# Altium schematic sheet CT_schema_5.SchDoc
size 296 x 173 mm
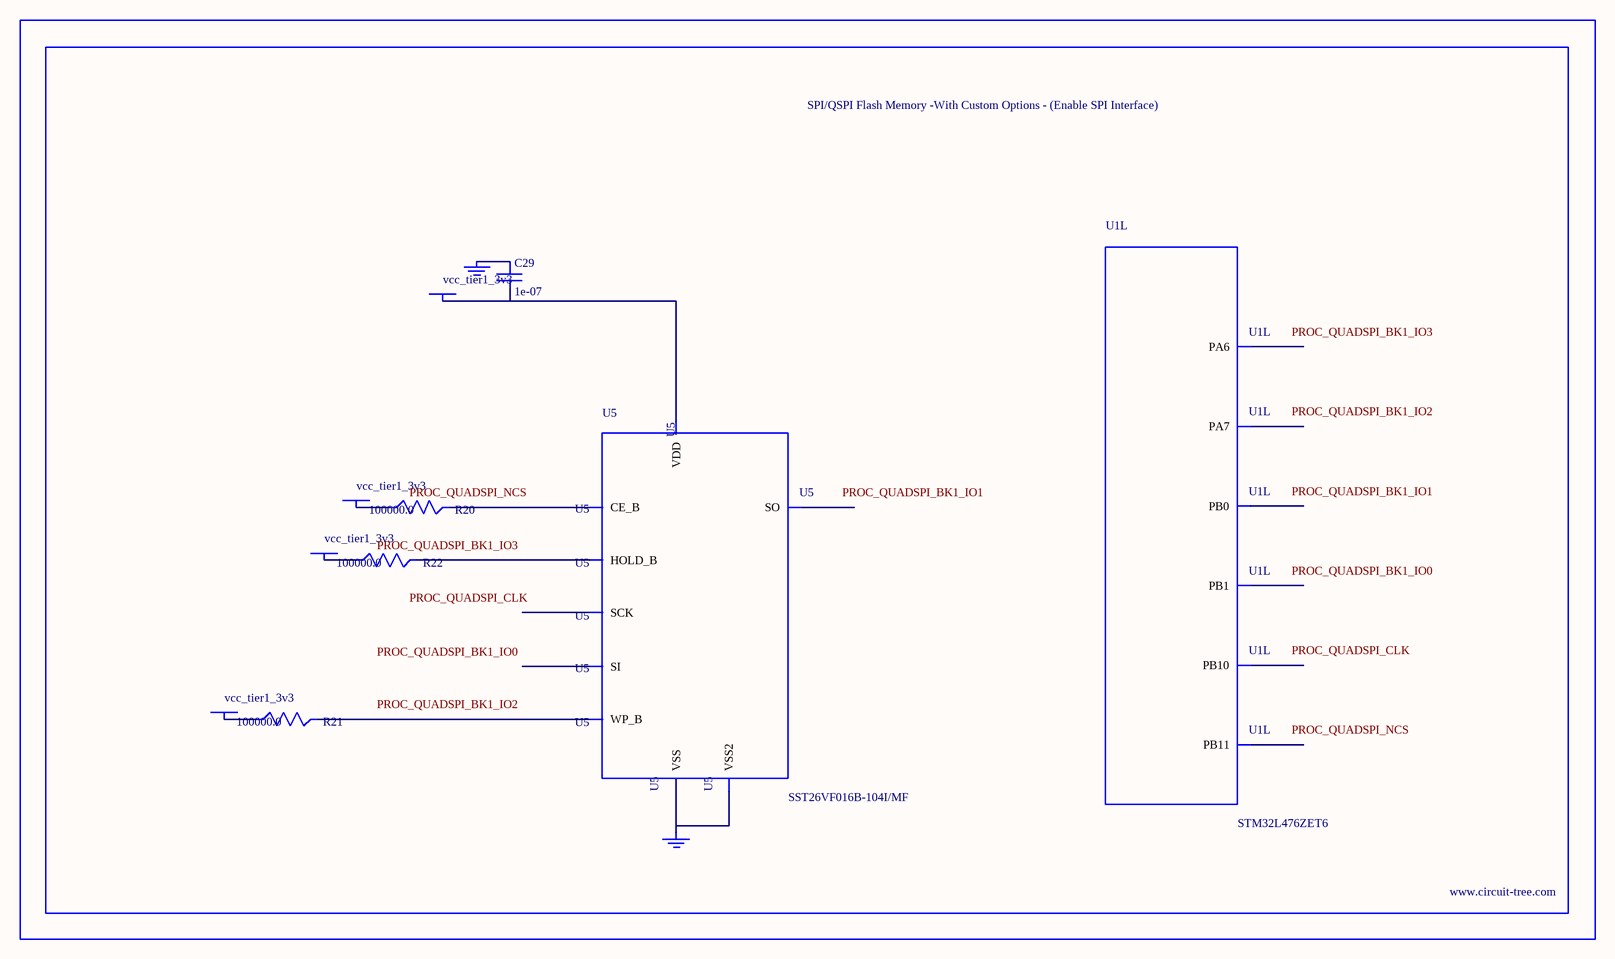
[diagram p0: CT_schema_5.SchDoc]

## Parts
BORDER4  (no value)
C29  1e-07  [C0402]
GND_INSTANCE_4_0  (no value)
GND_INSTANCE_4_1  (no value)
POWER_INSTANCE_4_0  vcc_tier1_3v3
POWER_INSTANCE_4_1  vcc_tier1_3v3
POWER_INSTANCE_4_2  vcc_tier1_3v3
POWER_INSTANCE_4_3  vcc_tier1_3v3
R20  100000.0  [R0603]
R21  100000.0  [R0603]
R22  100000.0  [R0603]
U1  STM32L476ZET6  [LQFP144]  (part L of 13)
U5  SST26VF016B-104I/MF  [WFDN-8]

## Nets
NetC29_1: C29.1 GND_INSTANCE_4_0.0(GND)
NetC29_2: C29.2 POWER_INSTANCE_4_3.0(PWR) U5.8(VDD)
NetGND_INSTANCE_4_1_0: GND_INSTANCE_4_1.0(GND) U5.4(VSS) U5.9(VSS2)
NetPOWER_INSTANCE_4_0_0: POWER_INSTANCE_4_0.0(PWR) R20.1
NetPOWER_INSTANCE_4_1_0: POWER_INSTANCE_4_1.0(PWR) R21.1
NetPOWER_INSTANCE_4_2_0: POWER_INSTANCE_4_2.0(PWR) R22.1
NetR20_2: R20.2 U5.1(CE_B)
NetR21_2: R21.2 U5.3(WP_B)
NetR22_2: R22.2 U5.7(HOLD_B)

Not connected (* = marked no-connect by the designer): U1 42(PA6) 43(PA7) 46(PB0) 47(PB1) 69(PB10) 70(PB11); U5 2(SO) 5(SI) 6(SCK)

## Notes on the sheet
- Labels drawn without touching a wire or pin: PROC_QUADSPI_BK1_IO0, PROC_QUADSPI_BK1_IO1, PROC_QUADSPI_BK1_IO2, PROC_QUADSPI_BK1_IO3, PROC_QUADSPI_CLK, PROC_QUADSPI_NCS

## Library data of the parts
BORDER4 = BORDER_PAGE4
C29 = C0402C104K3RACTU
GND_INSTANCE_4_0 GND_INSTANCE_4_1 = GND
POWER_INSTANCE_4_0-POWER_INSTANCE_4_3 = PWR
R20-R22 = RC0603JR-07100KL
